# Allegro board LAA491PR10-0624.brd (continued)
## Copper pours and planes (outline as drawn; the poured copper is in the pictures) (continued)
SNB_VDDCI on BOTTOM (solid shape): 183.04,177.56 183.04,175.84 182.97,175.78 180.75,175.78 180.62,175.91 180.62,176.54 180.69,176.6 181.7,176.6 181.83,176.73 181.83,177.56 181.89,177.62 182.97,177.62
SNUB_PCIE on TOP (solid shape): 197.96,66.74 197.96,64.81 197.85,64.7 196.86,64.7 196.78,64.79 196.78,65.5 196.71,65.57 195.96,65.57 195.75,65.77 195.75,66.83 195.87,66.96 197.74,66.96
SW_1.35V on TOP (solid shape): 154.66,16.85 154.66,15.64 154.72,15.58 154.72,15.33 154.59,15.2 153.77,15.2 153.58,15.39 153.58,16.79 153.77,16.98 154.53,16.98
SW_1.35V on TOP (solid shape): 157.39,23.64 157.39,23.39 156.37,22.37 156.06,22.37 155.74,22.69 155.74,23.14 156.44,23.84 157.2,23.84
SW_1.35V on BOTTOM (solid shape): 157.39,24.08 157.39,23.39 156.82,22.82 156.82,21.36 156.56,21.1 156.06,21.1 155.93,21.23 155.93,23.33 156.47,23.87 156.47,24.06 156.56,24.15 157.32,24.15
SW_1.35V on BOTTOM (solid shape): 155.16,17.73 155.16,15.32 155.93,14.55 155.93,11.69 156.05,11.57 156.56,11.57 156.68,11.44 156.68,10.93 156.62,10.87 154.1,10.87 152.37,12.6 150.34,12.6 149.96,12.98 149.96,16.6 150.72,17.36 153.07,17.36 153.5,17.79 153.51,17.79 153.57,17.85 155.03,17.85
SW_+1.2VSP on TOP (solid shape): 176.88,172.73 176.88,171.46 177.07,171.27 177.59,171.27 178.2,171.27 179.42,171.27 179.48,171.21 179.48,170.37 179.38,170.27 179.09,170.27 178.85,170.03 178.85,167.51 178.69,167.36 175.38,167.36 175.1,167.64 175.1,172.67 175.23,172.79 176.81,172.79
SW_+1.2VSP on TOP (solid shape): 185.7,172.35 185.7,172.22 185.64,172.16 184.81,172.16 184.69,172.03 184.44,172.03 184.38,171.97 184.37,171.97 184.12,171.71 183.87,171.71 183.8,171.71 183.67,171.59 183.67,171.4 183.54,171.27 182.72,171.27 182.66,171.33 182.66,171.9 183.16,172.41 185.64,172.41
SW_+1.2VSP on BOTTOM (solid shape): 179.42,175.02 179.42,168.03 179.1,167.71 179.09,167.71 178.69,167.32 175.35,167.32 174.78,167.89 174.78,172.27 177.66,172.27 177.67,172.22 177.68,172.16 177.7,172.11 177.73,172.07 177.77,172.01 177.77,171.98 177.77,171.95 177.73,171.89 177.7,171.85 177.68,171.8 177.67,171.75 177.66,171.69 177.67,171.64 177.68,171.59 177.7,171.54 177.72,171.49 177.76,171.45 177.8,171.41 177.84,171.38 177.89,171.36 177.94,171.34 177.99,171.33 178.05,171.33 178.1,171.34 178.15,171.36 178.2,171.38 178.24,171.41 178.28,171.45 178.32,171.49 178.34,171.54 178.36,171.59 178.37,171.64 178.38,171.69 178.37,171.75 178.36,171.8 178.34,171.85 178.31,171.89 178.27,171.95 178.27,171.98 178.27,172.01 178.31,172.07 178.34,172.11 178.36,172.16 178.37,172.22 178.38,172.27 178.37,172.32 178.36,172.37 178.34,172.42 178.32,172.47 178.28,172.51 178.24,172.55 178.2,172.58 178.15,172.6 178.1,172.62 178.05,172.63 177.99,172.63 177.94,172.62 177.89,172.6 177.84,172.58 177.8,172.55 177.76,172.51 177.72,172.47 177.7,172.42 177.68,172.37 177.67,172.32 177.66,172.27 174.78,172.27 174.78,175.21 174.97,175.4 179.04,175.4
SW_+1.2VSP on IN1 (solid shape): 179.73,171.02 180.56,171.02 180.69,170.89 180.69,170.44 180.5,170.25 179.23,170.25 179.04,170.44 179.04,171.14 179.23,171.33 179.42,171.33
SW_+1.2VSP on IN1 (solid shape): 184.75,172.35 184.75,172.1 184.63,171.97 184.6,171.98 184.53,171.98 184.45,171.97 184.13,171.97 183.99,171.97 183.35,171.33 182.91,171.33 182.78,171.46 182.78,171.84 183.42,172.48 184.62,172.48
SW_CPU2 on BOTTOM (solid shape): 112.36,143.19 112.36,140.7 110.93,140.7 110.65,140.41 110.65,139.2 110.46,139.01 109.38,139.01 109.19,138.82 109.19,138.19 109.12,138.12 106.17,138.12 106.14,138.16 106.14,139.77 108.32,139.77 108.32,140.54 106.14,140.54 106.14,142.82 106.65,143.33 112.22,143.33
SW_VGA_CORE on TOP (solid shape): 206.66,76.97 206.66,76.12 206.4,75.87 206.4,72.76 206.11,72.46 203.48,72.46 203.17,72.15 203.17,70.69 203.42,70.43 206.08,70.43 206.47,70.05 206.47,66.94 206.46,66.94 206.46,66.74 206.25,66.53 203.32,66.53 202.09,67.76 202.09,77.16 202.25,77.32 206.31,77.32
SW_VGA_CORE on BOTTOM (solid shape): 204.56,61.86 204.56,60.8 204.49,60.58 204.56,60.36 204.56,60.08 204.69,59.95 204.69,58.87 204.63,58.82 204.54,58.82 204.48,58.88 204.48,59.85 204.25,60.08 204.18,60.08 204.06,60.21 204.06,60.9 204.05,61.03 203.86,61.22 203.55,61.22 203.48,61.29 203.48,62.05 203.55,62.11 204.31,62.11
SW_VGA_CORE on BOTTOM (solid shape): outline of 156 points within 202.09,61.16 213.72,76.99
SW_VGA_CORE on IN1 (solid shape): 205.45,62.75 205.45,62.43 204.63,61.61 204.63,60.21 204.44,60.02 204.12,60.02 204.05,60.08 204.05,62.68 204.31,62.94 205.26,62.94
SW_VGA_CORE on IN1 (solid shape): 206.85,77.04 206.85,75.89 206.28,75.32 206.28,66.94 206.02,66.69 203.36,66.69 202.98,67.07 202.98,70.3 203.1,70.43 205.2,70.43 205.39,70.62 205.39,72.08 205.07,72.4 202.34,72.4 202.09,72.65 202.09,76.46 203.1,77.48 206.4,77.48
SW_VGA_CORE on IN2 (solid shape): 206.85,77.04 206.85,75.89 206.28,75.32 206.28,66.94 206.02,66.69 203.23,66.69 202.98,66.94 202.98,70.24 203.17,70.43 205.2,70.43 205.39,70.62 205.39,72.08 205.07,72.4 202.28,72.4 202.09,72.59 202.09,76.46 203.1,77.48 206.4,77.48
SW_VGA_CORE on IN3 (solid shape): 206.85,77.04 206.85,75.89 206.28,75.32 206.28,66.94 206.02,66.69 203.17,66.69 202.85,67 202.85,70.18 203.1,70.43 205.2,70.43 205.39,70.62 205.39,72.08 205.07,72.4 202.34,72.4 202.09,72.65 202.09,76.46 203.1,77.48 206.4,77.48
UG_3V on TOP (solid shape): 133.7,29.22 133.7,28.52 133.51,28.33 132.74,28.33 132.55,28.52 132.55,29.25 132.65,29.35 133.57,29.35
UG_3V on TOP (solid shape): 130.2,18.07 130.2,17.82 129.82,17.44 129.82,16.93 129.76,16.87 128.87,16.87 128.87,16.99 128.87,17.13 128.87,17.57 129.66,18.35 129.92,18.35
UG_3V on IN1 (solid shape): 131.09,18.66 131.09,18.54 129.68,17.12 129.07,17.12 128.93,17.26 128.93,17.53 130.5,19.09 130.66,19.09
UG_3V on IN1 (solid shape): 133.66,29.25 133.66,27.85 133.47,27.66 132.84,27.66 132.59,27.92 132.59,29.25 132.71,29.38 133.54,29.38
UG_5V on TOP (solid shape): 126.78,17.44 126.78,16.9 126.65,16.77 125.89,16.77 125.44,17.22 125.44,17.54 125.62,17.71 126.5,17.71
UG_5V on TOP (solid shape): 122.33,26.87 122.33,26.05 122.11,25.82 120.74,25.82 120.62,25.95 120.62,26.84 120.74,26.96 122.24,26.96
UG_5V on IN1 (solid shape): 125.76,17.69 126.65,17.69 126.71,17.63 126.71,17.31 126.46,17.06 124.81,17.06 124.64,17.22 124.64,17.66 124.88,17.9 125.55,17.9
UG_5V on IN1 (solid shape): 121.31,26.9 121.31,26.07 121.89,25.5 121.89,25.25 121.76,25.12 121.19,25.12 120.49,25.82 120.49,26.9 120.62,27.03 121.19,27.03
UG_+1.2VSP on TOP (solid shape): 178.27,172.35 178.27,171.52 178.15,171.4 177.64,171.4 177.13,171.9 177.13,172.6 177.26,172.73 177.89,172.73
UG_+1.2VSP on TOP (solid shape): 185.77,171.84 185.77,171.71 185.64,171.59 184.88,171.59 184.37,171.08 183.99,171.08 183.8,171.27 183.8,171.46 183.93,171.59 184.18,171.59 184.46,171.87 184.48,171.87 184.57,171.87 184.65,171.9 184.66,171.9 185.7,171.9
UG_+1.2VSP on IN1 (solid shape): 178.46,172.48 178.46,170.76 178.34,170.63 177.7,170.63 177.58,170.76 177.58,172.41 177.77,172.6 178.34,172.6
UG_+1.2VSP on IN1 (solid shape): 184.75,171.78 184.75,171.02 183.8,170.06 183.54,170.06 183.26,170.35 183.26,170.92 184.18,171.84 184.69,171.84
UG_VGA_CORE on TOP (solid shape): 206.4,71.64 206.4,71.45 206.21,71.26 203.8,71.26 203.67,71.38 203.67,71.83 203.8,71.96 206.09,71.96
UG_VGA_CORE on TOP (solid shape): 206.4,65.91 206.4,65.47 206.21,65.28 204.05,65.28 203.8,65.53 203.8,65.97 203.99,66.16 206.15,66.16
UG_VGA_CORE on BOTTOM (solid shape): 203.93,60.84 203.93,60.14 204.18,59.89 204.25,59.89 204.3,59.84 204.3,58.86 204.25,58.81 204.12,58.81 204.05,58.87 204.05,59.07 203.1,60.02 203.1,60.72 203.36,60.97 203.8,60.97
UG_VGA_CORE on IN1 (solid shape): 204.94,71.77 204.94,71.13 204.69,70.88 202.85,70.88 202.47,70.5 202.47,66.88 203.04,66.3 204.75,66.3 205.01,66.05 205.01,65.22 204.82,65.03 204.18,65.03 203.86,64.72 203.86,59.98 203.78,59.9 203.1,59.9 202.78,60.21 202.78,64.34 201.39,65.73 201.39,71.38 201.96,71.96 204.75,71.96
VCIN1_PH on TOP (solid shape): 130.31,181.93 130.31,178.13 130.21,178.03 129.77,178.03 129.61,178.19 129.61,181.97 129.66,182.01 130.22,182.01
N16988653 on BOTTOM (solid shape): 215.65,91.89 215.65,90.87 216.07,90.45 217.77,90.45 218.02,90.21 218.02,89.04 217.85,88.87 215.05,88.87 214.33,89.59 214.33,90.16 214.85,90.16 214.86,90.16 214.86,90.67 214.85,90.67 214.85,90.69 214.33,90.69 214.33,90.94 214.85,90.94 214.85,90.96 214.86,90.96 214.86,91.47 214.85,91.48 214.33,91.48 214.33,91.9 214.47,92.03 215.52,92.03
N16988706 on BOTTOM (solid shape): 216.56,94.05 216.56,93.36 216.95,92.97 216.95,92.4 216.88,92.34 216.37,92.34 215.6,93.12 215.6,94.05 215.66,94.12 216.5,94.12
N17002625 on BOTTOM (solid shape): 177.51,186.76 177.51,186.19 177.45,186.13 175.42,186.13 175.29,186.26 175.29,186.83 175.35,186.89 177.38,186.89
N17045846 on BOTTOM (solid shape): 202.85,62.11 202.85,61.29 202.72,61.16 200.94,61.16 200.88,61.22 200.88,61.8 200.94,61.86 201.64,61.86 201.96,62.18 202.78,62.18
N17046121 on BOTTOM (solid shape): 215.29,62.05 215.29,61.16 215.17,61.03 213.71,61.03 213.45,61.29 213.45,61.99 213.64,62.18 215.17,62.18
N17046121 on BOTTOM (solid shape): 215.61,67.89 215.61,67.13 215.42,66.94 213.77,66.94 213.52,67.19 213.52,67.64 213.67,67.8 214.56,67.8 214.79,68.02 215.48,68.02
N17046121 on BOTTOM (solid shape): 205.64,60.97 205.64,60.21 205.5,60.06 205.5,58.87 205.43,58.81 205.35,58.81 205.28,58.88 205.28,60.06 205.13,60.21 205.13,60.37 205.14,60.38 205.2,60.58 205.13,60.78 205.13,60.97 205.26,61.1 205.52,61.1
N17046121 on IN3 (solid shape): 207.04,61.1 207.04,60.46 206.66,60.08 205.26,60.08 205.13,60.21 205.13,60.37 205.14,60.38 205.2,60.58 205.14,60.77 205.13,60.78 205.13,60.91 205.32,61.1 206.4,61.1 206.66,61.35 206.79,61.35
N17046121 on IN3 (solid shape): 215.55,67.96 215.55,67.07 215.42,66.94 214.79,66.94 214.72,66.88 214.72,62.43 214.98,62.18 215.29,62.18 215.36,62.11 215.36,61.22 215.23,61.1 212.56,61.1 212.18,61.48 212.18,62.05 212.44,62.3 213.14,62.3 213.45,62.62 213.45,67.76 213.71,68.02 215.48,68.02
N17608587 on BOTTOM (solid shape): 149.38,158.22 149.38,157.29 148.95,156.86 148.95,156.6 148.75,156.4 148.12,156.4 148.12,158.56 149.04,158.56
N18009264 on BOTTOM (solid shape): 148.05,164.92 148.05,161.36 147.54,160.86 142.71,160.86 142.65,160.92 142.65,161.77 142.72,161.83 144.09,161.83 144.44,162.19 144.09,162.55 142.74,162.55 142.59,162.7 142.59,163.27 142.65,163.33 144.75,163.33 145.38,163.97 145.38,164.79 145.7,165.11 147.86,165.11
N18009411 on BOTTOM (solid shape): 148.05,183.83 148.05,182.63 147.79,182.37 146.41,182.37 146.21,182.57 146.21,182.83 146.4,183.02 146.9,183.02 147.03,183.14 147.03,184.16 147.16,184.28 147.6,184.28
N18009417 on TOP (solid shape): 157,177.77 157,176.18 156.87,176.06 154.91,176.06 154.72,176.25 154.72,176.76 154.78,176.82 155.48,176.82 155.73,177.07 155.73,177.77 155.86,177.9 156.87,177.9
N18284053 on BOTTOM (solid shape): 138.15,176.66 138.15,174.13 137.91,173.89 135.94,173.89 135.41,173.35 135.41,170.13 137.95,167.59 137.95,165.55 137.81,165.41 135.33,165.41 135.03,165.71 135.03,165.9 133.03,167.9 133.03,174.35 135.63,176.95 137.87,176.95
N19792312 on BOTTOM (solid shape): 24.27,27.21 24.27,26.32 24.13,26.18 22.56,26.18 22.51,26.23 22.51,26.88 22.95,27.32 24.17,27.32
N21178712 on TOP (solid shape): 132.14,174.01 132.14,172.45 132.04,172.36 129.89,172.36 129.27,172.97 129.27,174.2 129.35,174.28 131.87,174.28
N21457125 on TOP (solid shape): 23.9,90.74 23.9,78.8 23.84,78.74 22.13,78.74 22.06,78.8 22.06,79.94 23.08,80.96 23.08,90.74 23.21,90.87 23.78,90.87
N23098273 on TOP (solid shape): 39.08,111.44 39.08,109.6 38.8,109.31 37.4,109.31 37.18,109.54 37.18,111.38 37.43,111.63 38.89,111.63
N23098273 on BOTTOM (solid shape): 42.03,111.09 43.96,111.09 44.14,110.9 44.14,105.1 43.87,104.83 42.93,104.83 42.85,104.83 42.85,105.35 42.34,105.35 42.34,104.83 42.05,104.83 42.05,105.35 41.54,105.35 41.54,104.83 41.09,104.83 40.9,105.02 40.9,108.67 40.43,109.15 37.38,109.15 37.18,109.35 37.18,111.5 37.41,111.74 41.38,111.74
N32320781 on BOTTOM (solid shape): 140.81,164.41 141.7,163.52 141.7,162.63 141.7,162.63 141.7,162.55 140.33,162.55 139.97,162.19 140.33,161.83 141.69,161.83 141.7,161.83 141.7,161.17 141.44,160.92 138.71,160.92 138.27,161.36 138.27,164.92 138.71,165.36 140.81,165.36
N46608740 on BOTTOM (solid shape): 142.33,167.02 143.09,167.02 143.22,166.89 143.22,165.43 143.16,165.36 142.27,165.36 142.08,165.55 138.59,165.55 138.35,165.79 138.35,167.28 138.54,167.46 141.89,167.46
N46660696 on TOP (solid shape): 109.12,144.03 109.12,142.57 108.87,142.31 107.98,142.31 107.85,142.44 107.85,143.2 107.66,143.39 107.03,143.39 106.9,143.52 106.9,144.03 107.03,144.16 109,144.16
N47008006 on TOP (solid shape): 129.18,177.77 129.18,176.3 129.08,176.2 129.08,174.62 128.98,174.51 128.1,174.51 128,174.62 128,177.75 128.16,177.91 129.04,177.91
N47008301 on TOP (solid shape): 129.44,179.52 129.44,178.45 129.27,178.28 127.98,178.28 127.75,178.51 127.75,179.68 127.92,179.85 129.12,179.85
N47305899 on TOP (solid shape): 211.74,63.45 211.74,61.86 211.67,61.8 210.15,61.8 209.58,62.37 209.58,63.32 209.77,63.51 211.67,63.51
N47415258 on TOP (solid shape): 135.79,21.63 134.7,20.54 132.56,20.54 132.3,20.8 132.3,21.76 132.43,21.88 133.63,21.88 134.14,22.39 134.14,22.71 135.79,22.71
N47415272 on TOP (solid shape): 120.87,22.84 120.87,22.2 120.92,22.15 121.9,22.15 122.01,22.04 122.01,20.93 121.89,20.8 119.73,20.8 119.16,21.38 119.16,22.9 120.81,22.9
N47417471 on BOTTOM (solid shape): 109.99,24.55 109.99,23.79 110.12,23.66 110.12,21.07 109.76,20.71 108.95,20.71 108.95,21.23 108.44,21.23 108.44,20.71 108.15,20.71 108.15,21.23 107.64,21.23 107.64,20.71 107.03,20.71 106.46,21.28 106.46,23.44 106.99,23.98 108.79,23.98 109.1,23.66 109.61,23.66 109.74,23.79 109.74,24.55 109.8,24.62 109.93,24.62
N47420895 on BOTTOM (solid shape): 161.83,11.5 161.83,9.92 161.76,9.85 160.62,9.85 159.73,10.74 157.12,10.74 156.98,10.87 156.98,11.42 157.06,11.5 160.62,11.5 160.68,11.57 161.76,11.57
N64564173 on TOP (solid shape): 183.61,170.57 183.61,170 184.05,169.56 184.05,168.73 183.99,168.67 183.35,168.67 183.23,168.79 183.23,169.36 182.72,169.87 182.72,170.57 182.78,170.63 183.54,170.63
N64564191 on TOP (solid shape): 180.75,171.33 180.75,170.7 181,170.44 181.7,170.44 181.83,170.32 181.83,169.62 181.7,169.49 179.8,169.49 179.67,169.62 179.67,171.27 179.8,171.4 180.69,171.4

Small or netless copper shapes (teardrops, artwork), in the pictures only: 20 on TOP, 349 on BOTTOM, 1 on IN1

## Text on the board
Ref Des/Silkscreen Bottom: Jack | Audio | H10 | JDIMM1 | FAN | OnlysupportDDR3L | JDIMM2 | H7 | CardReader | H6 | RTC Battery | HDD
User.Comments: LAA491P | 2013-06-24 | 2014-06-24 | ZAL00 | Win
Ref Des/Silkscreen Top: CRT | Touch | USB2.0 | USB3.0 | RJ45 | Screen | Power | Button | Touch Pad | Speaker | WiFi+BT | Cable | DC-IN | Battery | LCD Panel | Keyboard | ODD
BODY_CENTER: Width/space | 85 ohm | 5 / 5.5 | 4.5/5.5 | 4 / 6.5 | 5 / 8 | 100 ohm | 4 / 12 | 4 / 8 | SB_1_2mm-6L and 8L and 10L(4mil & 5mil 50ohm)_120807
COMPVAL_TYPE_TOP: FIGURE | SIZE | 8.0 | 10.0 | 24.0 | 28.0 | 31.0 | 35.0 | 36.0 | 39.0 | 91.0 | 110.0 | 130.0 | 146.0 | 40.0 | 43.0 | 47.0 | 63.0 | 71.0 | 28.0x16.0 | 59.0x24.0 | 63.0x28.0 | 71.0x20.0 | 71.0x31.0 | 79.0x31.0 | 91.0x35.0 | 94.0x39.0 | 106.0x31.0 | 110.0x39.0 | 146.0x126.0 | DRILL CHART: TOP to BOTTOM | ALL UNITS ARE IN MILS | PLATED | NON-PLATED | QTY | 5031 | 714 | 6 | 40 | 22 | 8 | 4 | 9 | 2 | 1 | 7 | 26
User.20: 217.12 | 214.88 | 212.51 | 209.10 | 213.45 | 179.85 | 155.58 | 158.85 | 131.90 | 69.68 | 14.60 | 0.00 | 1.85 | 3.45 | SCALE | 1.000 | 12.70 | 27.00 | 44.60 | 62.20 | 17.00 | 81.47 | 90.60 | 103.25 | 105.45 | 145.77 | 32.50 | 40.80 | 93.32 | 154.95 | 183.80
User.21: 183.05 | 174.00 | 104.45 | 88.30 | 55.01 | 16.00 | 1.25 | 103.70 | 58.34 | 24.93 | 4.55 | 168.55 | 173.50
User.24: 2.80 | n | 9.00 | 6.00 | 3.70 | 8.00 | 3.30 | 2.30 | 3.20 | 5.80
User.25: 203.30 | 198.28 | 194.00 | 144.40 | 116.00 | 97.60 | 84.00 | 71.90 | 61.00 | 29.40 | 21.10 | 2.60 | 0.00 | 149.90 | 114.20 | 104.50 | 98.76 | 67.00 | 33.20 | 8.50 | 76.50 | 89.50 | 89.55 | 115.85 | 124.16 | 139.60 | 163.50 | 182.60
User.26: WHITE PAINT
User.27: WHITE PAINT
User.28: 0.00
User.38: GND | GNDA | +5VALW | +3VS | +CPU_CORE | +3VALW | +5VS | +1.05VS | +VDDCI | +1.35VS_VGA | +VGA_CORE
